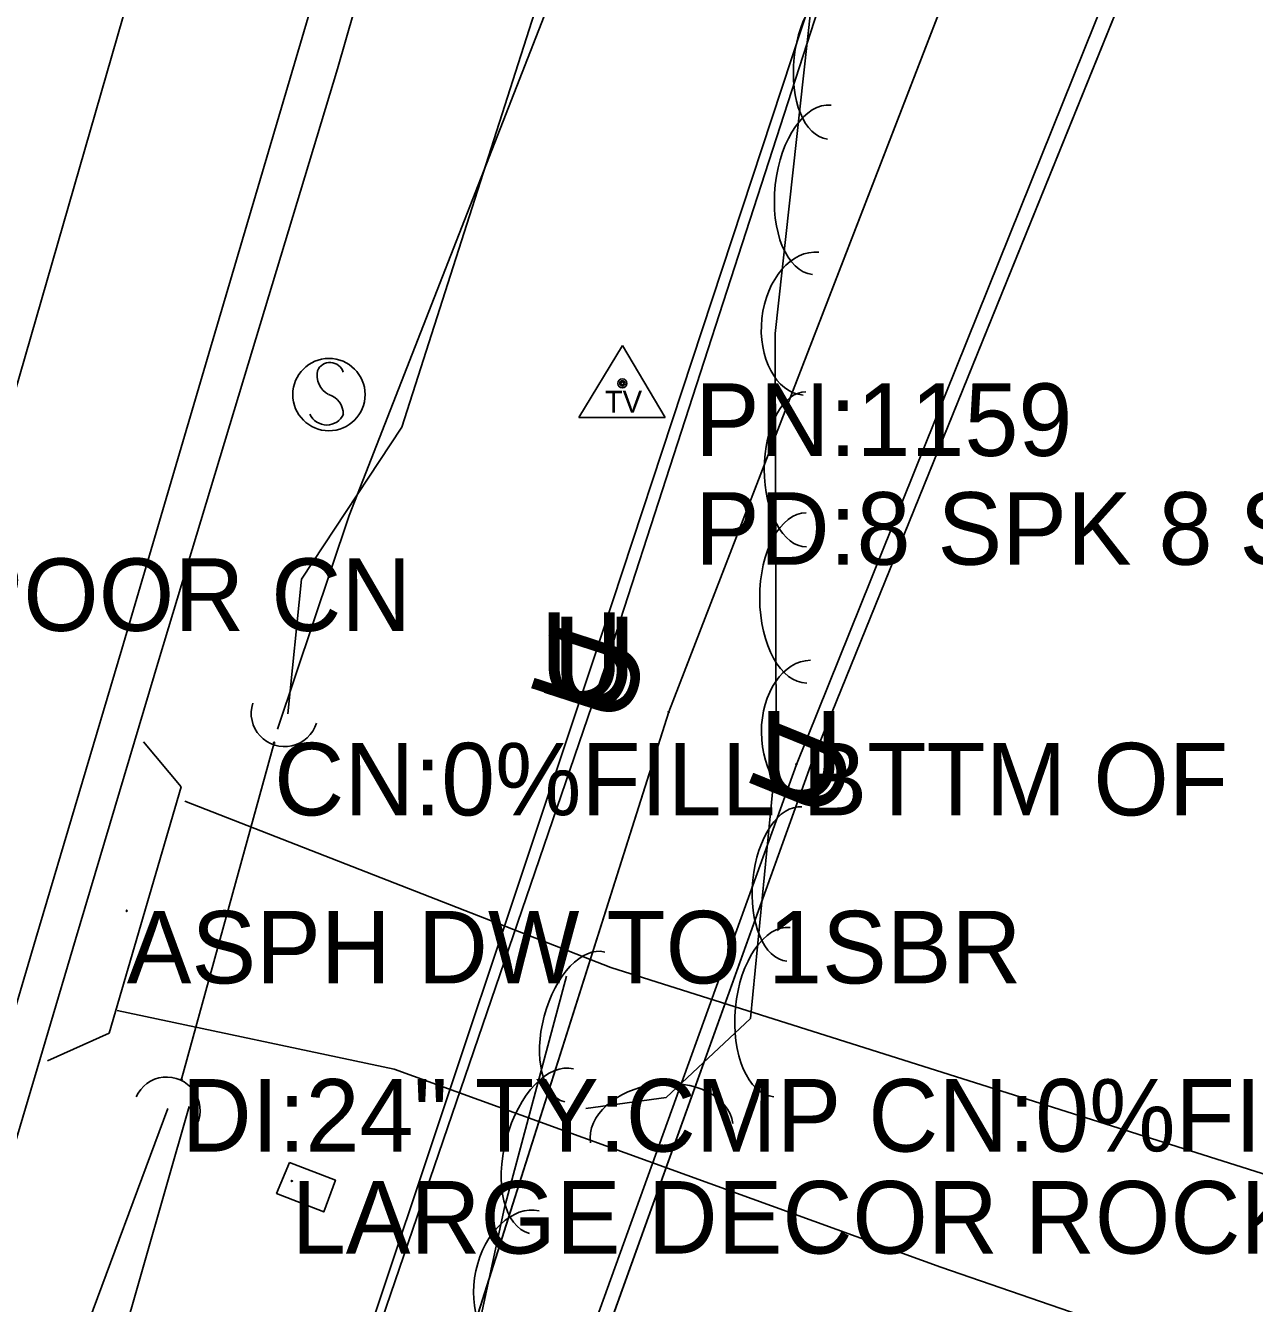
# Model space of a CAD drawing. Extents: x 954793 to 988390, y 1867850 to 1924428.
# Drawn here: x 961111.1 to 961195.8, y 1905934.5 to 1906022.6 of the extents above; entities that cross this region are included whole.
import ezdxf

# ---------------------------------------------------------------- set-up
doc = ezdxf.new("R2010")
doc.units = 0
for name, color, linetype in [('Default', 7, 'Continuous'), ('S_CROSS_DRAIN', 7, 'Continuous'), ('S_DITCHLINE', 7, 'Continuous'), ('S_DRG_PT_SYM', 7, 'Continuous'), ('S_DRIVEWAY', 7, 'Continuous'), ('S_EDGE_CONCRETE', 7, 'Continuous'), ('S_EDGE_PAVEMENT', 7, 'Continuous'), ('S_FIBER_OPTIC_CABLE', 7, 'Continuous'), ('S_MSC_PT_SYM', 7, 'Continuous'), ('S_PAVEMENT_CROWN', 7, 'Continuous'), ('S_SECONDARY_CTL', 7, 'Continuous'), ('S_SECONDARY_CTL_ANNOT', 7, 'Continuous'), ('S_SHOULDER', 7, 'Continuous'), ('S_SIDE_DRAIN', 7, 'Continuous'), ('S_SIDE_DRAIN_ANNOT', 7, 'Continuous'), ('S_SIGN', 7, 'Continuous'), ('S_STREAM', 7, 'Continuous'), ('S_SURVEY_TEXT_ANNOT', 7, 'Continuous'), ('S_TREE', 7, 'Continuous'), ('S_UNDERGROUND_CABLE', 7, 'Continuous'), ('S_UTL_PT_SYM', 7, 'Continuous'), ('S_WATER_UTILITIES', 7, 'Continuous')]:
    doc.layers.add(name, color=color, linetype=linetype)

msp = doc.modelspace()

# ---------------------------------------------------------------- linework, layer by layer
at = {"layer": 'S_CROSS_DRAIN'}
for centre, start, end in [((961128.96, 1905975.23), 162.58525, 342.91443), ((961120.837, 1905947.85), 335.96527, 156.29446)]:
    msp.add_arc(centre, 2.3, start, end, dxfattribs=at)
at = {"layer": 'S_DITCHLINE'}
for points in [[(961129.18, 1905975.188), (961130.136, 1905984.462), (961137.044, 1905994.957), (961141.521, 1906008.944), (961145.998, 1906022.932), (961150.474, 1906036.919), (961154.951, 1906050.907), (961160.816, 1906068.656), (961166.682, 1906086.405), (961172.547, 1906104.154), (961178.413, 1906121.903), (961184.86, 1906136.474), (961191.308, 1906151.044), (961194.924, 1906165.194)], [(961060.215, 1905744.943), (961065.303, 1905762.405), (961070.391, 1905779.868), (961075.479, 1905797.33), (961080.567, 1905814.792), (961085.085, 1905834.323), (961090.929, 1905858.605), (961096.773, 1905882.887), (961102.809, 1905899.163), (961108.845, 1905915.438), (961114.881, 1905931.714), (961120.917, 1905947.989)], [(961061.183, 1905744.784), (961066.495, 1905762.214), (961071.808, 1905779.644), (961077.121, 1905797.073), (961082.433, 1905814.503), (961090.136, 1905832.773), (961096.66, 1905856.896), (961103.185, 1905881.019), (961107.984, 1905897.792), (961112.783, 1905914.564), (961117.581, 1905931.337), (961122.38, 1905948.109)]]:
    msp.add_lwpolyline(points, dxfattribs=at)
at = {"layer": 'S_DRG_PT_SYM'}
for points in [[(961128.243, 1905973.187), (961128.243, 1905973.237), (961128.243, 1905973.187), (961128.193, 1905973.187), (961128.243, 1905973.187), (961128.243, 1905973.137), (961128.243, 1905973.187), (961128.293, 1905973.187)], [(961121.864, 1905950.008), (961121.864, 1905950.058), (961121.864, 1905950.008), (961121.814, 1905950.008), (961121.864, 1905950.008), (961121.864, 1905949.958), (961121.864, 1905950.008), (961121.914, 1905950.008)]]:
    msp.add_lwpolyline(points, dxfattribs=at)
for points in [[(961128.243, 1905973.187), (961128.195, 1905973.2), (961128.243, 1905973.187), (961128.23, 1905973.139), (961128.243, 1905973.187), (961128.291, 1905973.174), (961128.243, 1905973.187), (961128.256, 1905973.235)], [(961128.243, 1905973.187), (961128.195, 1905973.2), (961128.243, 1905973.187), (961128.23, 1905973.139), (961128.243, 1905973.187), (961128.291, 1905973.174), (961128.243, 1905973.187), (961128.256, 1905973.235)], [(961121.864, 1905950.008), (961121.816, 1905950.022), (961121.864, 1905950.008), (961121.851, 1905949.96), (961121.864, 1905950.008), (961121.913, 1905949.995), (961121.864, 1905950.008), (961121.878, 1905950.057)], [(961121.864, 1905950.008), (961121.816, 1905950.022), (961121.864, 1905950.008), (961121.851, 1905949.96), (961121.864, 1905950.008), (961121.913, 1905949.995), (961121.864, 1905950.008), (961121.878, 1905950.057)]]:
    msp.add_lwpolyline(points, close=True, dxfattribs=at)
at = {"layer": 'S_DRIVEWAY'}
for points in [[(961119.246, 1905973.25), (961121.829, 1905970.159)], [(961116.874, 1905953.163), (961121.829, 1905970.159)], [(961296.101, 1905908.22), (961245.91, 1905924.921), (961198.101, 1905942.953), (961151.444, 1905957.691), (961122.087, 1905969.17)], [(961117.428, 1905954.727), (961136.52, 1905950.688), (961174.199, 1905937.044), (961189.272, 1905931.845), (961190.701, 1905910.589), (961190.902, 1905906.512), (961191.873, 1905904.938), (961194.153, 1905903.563), (961214.459, 1905896.764)], [(961112.615, 1905951.267), (961116.874, 1905953.163)]]:
    msp.add_lwpolyline(points, dxfattribs=at)
at = {"layer": 'S_EDGE_CONCRETE'}
msp.add_lwpolyline([(961129.301, 1905944.265), (961128.415, 1905942.127), (961131.658, 1905940.847), (961132.469, 1905943.044)], close=True, dxfattribs=at)
at = {"layer": 'S_EDGE_PAVEMENT'}
msp.add_lwpolyline([(961059.501, 1905778.095), (961063.196, 1905791.462), (961068.574, 1905810.915), (961074.557, 1905832.011), (961080.539, 1905853.106), (961086.72, 1905874.132), (961092.901, 1905895.158), (961099.405, 1905917.452), (961105.908, 1905939.746), (961111.82, 1905959.697), (961117.732, 1905979.649), (961123.745, 1906000.037), (961129.759, 1906020.426), (961135.778, 1906040.836), (961141.798, 1906061.247), (961146.962, 1906078.606), (961152.126, 1906095.965), (961158.226, 1906116.731), (961164.327, 1906137.496), (961170.227, 1906157.296), (961176.128, 1906177.097), (961181.983, 1906196.97), (961187.837, 1906216.843)], dxfattribs=at)
at = {"layer": 'S_FIBER_OPTIC_CABLE'}
for p, q in [((961164.243, 1905971.704), (961188.563, 1906032.157)), ((961132.892, 1905884.854), (961164.243, 1905971.704))]:
    msp.add_line(p, q, dxfattribs=at)
msp.add_lwpolyline([(961026.414, 1904948.637), (961017.369, 1904982.587), (961011.819, 1905055.257), (961016.601, 1905138.531), (961017.468, 1905193.437), (961017.277, 1905224.85), (961027.258, 1905262.094), (961046.136, 1905280.89), (961043.588, 1905375.147), (961039.349, 1905456.04), (961041.723, 1905513.175), (961045.689, 1905529.363), (961064.975, 1905556.232), (961068.353, 1905571.617), (961066.892, 1905584.495), (961064.167, 1905622.208), (961068.799, 1905682.724), (961097.338, 1905766.72), (961110.99, 1905817.563), (961132.892, 1905884.854), (961164.243, 1905971.704), (961188.563, 1906032.157), (961262.109, 1906149.746)], dxfattribs=at)
msp.add_lwpolyline([(961026.414, 1904948.637), (961017.369, 1904982.587), (961011.819, 1905055.257), (961016.601, 1905138.531), (961017.468, 1905193.437), (961017.277, 1905224.85), (961027.258, 1905262.094), (961046.136, 1905280.89), (961043.588, 1905375.147), (961039.349, 1905456.04), (961041.723, 1905513.175), (961045.689, 1905529.363), (961064.975, 1905556.232), (961068.353, 1905571.617), (961066.892, 1905584.495), (961064.167, 1905622.208), (961068.799, 1905682.724), (961097.338, 1905766.72), (961110.99, 1905817.563), (961132.892, 1905884.854), (961164.243, 1905971.704), (961188.563, 1906032.157), (961262.109, 1906149.746)], dxfattribs=at)
at = {"layer": 'S_MSC_PT_SYM'}
for points in [[(961118.082, 1905961.603), (961118.082, 1905961.653), (961118.082, 1905961.603), (961118.032, 1905961.603), (961118.082, 1905961.603), (961118.082, 1905961.553), (961118.082, 1905961.603), (961118.132, 1905961.603)], [(961118.082, 1905961.603), (961118.082, 1905961.653), (961118.082, 1905961.603), (961118.032, 1905961.603), (961118.082, 1905961.603), (961118.082, 1905961.553), (961118.082, 1905961.603), (961118.132, 1905961.603)], [(961129.459, 1905942.977), (961129.459, 1905943.027), (961129.459, 1905942.977), (961129.409, 1905942.977), (961129.459, 1905942.977), (961129.459, 1905942.927), (961129.459, 1905942.977), (961129.509, 1905942.977)], [(961129.459, 1905942.977), (961129.459, 1905943.027), (961129.459, 1905942.977), (961129.409, 1905942.977), (961129.459, 1905942.977), (961129.459, 1905942.927), (961129.459, 1905942.977), (961129.509, 1905942.977)]]:
    msp.add_lwpolyline(points, close=True, dxfattribs=at)
for points in [[(961118.082, 1905961.603), (961118.082, 1905961.653), (961118.082, 1905961.603), (961118.032, 1905961.603), (961118.082, 1905961.603), (961118.082, 1905961.553), (961118.082, 1905961.603), (961118.132, 1905961.603)], [(961129.459, 1905942.977), (961129.459, 1905943.027), (961129.459, 1905942.977), (961129.409, 1905942.977), (961129.459, 1905942.977), (961129.459, 1905942.927), (961129.459, 1905942.977), (961129.509, 1905942.977)]]:
    msp.add_lwpolyline(points, dxfattribs=at)
at = {"layer": 'S_PAVEMENT_CROWN'}
msp.add_lwpolyline([(961045.692, 1905774.257), (961051.222, 1905794.405), (961056.753, 1905814.553), (961062.701, 1905835.209), (961068.648, 1905855.865), (961074.923, 1905877.26), (961081.198, 1905898.655), (961087.38, 1905919.534), (961093.562, 1905940.414), (961099.888, 1905961.707), (961106.214, 1905983), (961112.203, 1906003.736), (961118.191, 1906024.473), (961123.855, 1906043.594), (961129.52, 1906062.715), (961135.06, 1906081.232), (961140.6, 1906099.749), (961146.853, 1906120.651), (961153.107, 1906141.553), (961158.918, 1906161.262), (961164.729, 1906180.972), (961170.649, 1906200.778), (961176.57, 1906220.585)], dxfattribs=at)
at = {"layer": 'S_SECONDARY_CTL'}
for p, q in [((961152.244, 1906000.578), (961149.234, 1905995.624)), ((961152.244, 1906000.578), (961155.191, 1905995.624)), ((961149.234, 1905995.624), (961155.191, 1905995.624))]:
    msp.add_line(p, q, dxfattribs=at)
for radius in [0.311, 0.183, 0.103]:
    msp.add_circle((961152.244, 1905997.968), radius, dxfattribs=at)
at = {"layer": 'S_SHOULDER'}
msp.add_lwpolyline([(961061.53, 1905777.008), (961065.543, 1905790.797), (961071.149, 1905810.063), (961077.06, 1905831.047), (961082.972, 1905852.032), (961089.167, 1905873.293), (961095.361, 1905894.554), (961102.078, 1905917.445), (961108.795, 1905940.336), (961114.544, 1905959.623), (961120.293, 1905978.91), (961126.454, 1905999.284), (961132.614, 1906019.658), (961138.502, 1906040.151), (961144.389, 1906060.644), (961149.609, 1906077.911), (961154.83, 1906095.178), (961161.033, 1906115.566), (961167.236, 1906135.953), (961169.91, 1906145.635), (961174.041, 1906161.079), (961178.172, 1906176.523), (961184.445, 1906196.28), (961190.718, 1906216.037)], dxfattribs=at)
at = {"layer": 'S_SIDE_DRAIN'}
msp.add_line((961121.864, 1905950.008), (961128.243, 1905973.187), dxfattribs=at)
msp.add_lwpolyline([(961121.864, 1905950.008), (961128.243, 1905973.187)], dxfattribs=at)
msp.add_lwpolyline([(961121.864, 1905950.008), (961128.243, 1905973.187)], dxfattribs=at)
at = {"layer": 'S_SIGN'}
msp.add_circle((961132.02, 1905997.198), 2.494, dxfattribs=at)
for centre, radius, start, end in [((961132.094, 1905998.466), 0.95, 16.52582, 156.89569), ((961132.706, 1905998.525), 1.503, 167.11961, 241.98129), ((961131.608, 1905995.856), 1.398, 358.65289, 73.70634), ((961131.867, 1905996.376), 1.275, 204.64102, 335.35898)]:
    msp.add_arc(centre, radius, start, end, dxfattribs=at)
at = {"layer": 'S_STREAM'}
msp.add_lwpolyline([(961128.481, 1905974.139), (961133.42, 1905988.873), (961146.853, 1906023.29), (961155.667, 1906050.873), (961167.729, 1906085.935), (961181.678, 1906131.246), (961190.307, 1906152.691), (961193.786, 1906159.569), (961195.042, 1906166.534)], dxfattribs=at)
at = {"layer": 'S_TREE'}
for points in [[(961149.717, 1905947.977), (961155.258, 1905948.73), (961161.079, 1905954.184), (961162.847, 1905972.394), (961162.769, 1906001.409), (961165.231, 1906023.769), (961167.597, 1906030.415), (961177.41, 1906046.959), (961187.224, 1906054.312), (961192.893, 1906070.61), (961195.056, 1906096.656), (961195.57, 1906124.78), (961197.722, 1906144.345), (961210.193, 1906184.689), (961219.088, 1906219.194)], [(961095.873, 1905771.677), (961101.648, 1905792.34), (961111.197, 1905822.337), (961117.452, 1905845.686), (961123.47, 1905862.287), (961140.579, 1905924.778), (961144.127, 1905941.149), (961148.391, 1905957.107)]]:
    msp.add_lwpolyline(points, dxfattribs=at)
for centre, major_axis, ratio in [((961166.963, 1906020.126), (-0.585, -5.314), 0.540699), ((961165.993, 1906011.311), (-0.642, -5.833), 0.55008), ((961165.24, 1906002.08), (-0.542, -4.926), 0.685311), ((961164.915, 1905992.048), (0.014, -5.346), 0.540699), ((961164.939, 1905983.18), (0.016, -5.868), 0.55008), ((961165.225, 1905973.922), (0.013, -4.955), 0.685311), ((961164.109, 1905963.448), (-0.517, -5.321), 0.540699), ((961163.252, 1905954.622), (-0.567, -5.841), 0.55008), ((961149.65, 1905953.6), (-1.38, -5.165), 0.540699), ((961147.36, 1905945.033), (-1.515, -5.67), 0.55008), ((961154.949, 1905946.284), (-4.91, -0.667), 0.685311), ((961145.466, 1905936.078), (-1.05, -4.843), 0.685311)]:
    msp.add_ellipse(centre, major_axis=major_axis, ratio=ratio, start_param=3.141593, end_param=6.283185, dxfattribs=at)
at = {"layer": 'S_UNDERGROUND_CABLE'}
for p, q in [((961150.178, 1905978.736), (961170.903, 1906041.604)), ((961151.052, 1905978.437), (961171.492, 1906041.573)), ((961165.317, 1905971.926), (961189.544, 1906031.665)), ((961122.683, 1905896.294), (961150.178, 1905978.736)), ((961122.935, 1905896.129), (961151.052, 1905978.437)), ((961133.816, 1905884.197), (961165.317, 1905971.926))]:
    msp.add_line(p, q, dxfattribs=at)
for points in [[(961017.856, 1904908.457), (961015.885, 1904941.507), (961005.937, 1904974.057), (960999.55, 1905055.876), (961001.902, 1905134.038), (961007.432, 1905195.766), (961009.84, 1905254.085), (961011.897, 1905344.409), (961013.819, 1905431.572), (961016.121, 1905461.565), (961020.884, 1905544.239), (961037.019, 1905625.358), (961046.38, 1905663.741), (961054.039, 1905678.824), (961068.032, 1905730.244), (961081.989, 1905759.219), (961099.968, 1905821.206), (961122.683, 1905896.294), (961150.178, 1905978.736), (961170.903, 1906041.604), (961202.059, 1906097.637), (961216.094, 1906117.433), (961239.648, 1906156.812)], [(961017.856, 1904908.457), (961015.885, 1904941.507), (961005.937, 1904974.057), (960999.55, 1905055.876), (961001.902, 1905134.038), (961007.432, 1905195.766), (961009.84, 1905254.085), (961011.897, 1905344.409), (961013.819, 1905431.572), (961016.121, 1905461.565), (961020.884, 1905544.239), (961037.019, 1905625.358), (961046.38, 1905663.741), (961054.039, 1905678.824), (961068.032, 1905730.244), (961081.989, 1905759.219), (961099.968, 1905821.206), (961122.683, 1905896.294), (961150.178, 1905978.736), (961170.903, 1906041.604), (961202.059, 1906097.637), (961216.094, 1906117.433), (961239.648, 1906156.812)], [(961018.521, 1904908.237), (961016.25, 1904941.651), (961006.406, 1904974.081), (961000.088, 1905055.791), (961002.591, 1905134.184), (961008.144, 1905195.509), (961010.364, 1905253.954), (961012.527, 1905344.234), (961014.305, 1905431.545), (961016.781, 1905461.41), (961021.243, 1905543.936), (961037.472, 1905625.323), (961046.9, 1905663.524), (961054.501, 1905678.7), (961068.525, 1905729.918), (961082.6, 1905758.887), (961100.338, 1905821.137), (961122.935, 1905896.129), (961151.052, 1905978.437), (961171.492, 1906041.573), (961202.633, 1906097.751), (961216.733, 1906116.832), (961239.626, 1906156.767)], [(961018.521, 1904908.237), (961016.25, 1904941.651), (961006.406, 1904974.081), (961000.088, 1905055.791), (961002.591, 1905134.184), (961008.144, 1905195.509), (961010.364, 1905253.954), (961012.527, 1905344.234), (961014.305, 1905431.545), (961016.781, 1905461.41), (961021.243, 1905543.936), (961037.472, 1905625.323), (961046.9, 1905663.524), (961054.501, 1905678.7), (961068.525, 1905729.918), (961082.6, 1905758.887), (961100.338, 1905821.137), (961122.935, 1905896.129), (961151.052, 1905978.437), (961171.492, 1906041.573), (961202.633, 1906097.751), (961216.733, 1906116.832), (961239.626, 1906156.767)], [(961062.236, 1905659.183), (961065.738, 1905659.369), (961069.924, 1905682.488), (961098.401, 1905766.49), (961112.008, 1905817.424), (961133.816, 1905884.197), (961165.317, 1905971.926), (961189.544, 1906031.665), (961255.496, 1906122.597), (961261.765, 1906150.054)], [(961062.236, 1905659.183), (961065.738, 1905659.369), (961069.924, 1905682.488), (961098.401, 1905766.49), (961112.008, 1905817.424), (961133.816, 1905884.197), (961165.317, 1905971.926), (961189.544, 1906031.665), (961255.496, 1906122.597), (961261.765, 1906150.054)]]:
    msp.add_lwpolyline(points, dxfattribs=at)
at = {"layer": 'S_UTL_PT_SYM'}
for points in [[(961155.443, 1905975.316), (961155.443, 1905975.366), (961155.443, 1905975.316), (961155.393, 1905975.316), (961155.443, 1905975.316), (961155.443, 1905975.266), (961155.443, 1905975.316), (961155.493, 1905975.316)], [(961164.243, 1905971.704), (961164.243, 1905971.754), (961164.243, 1905971.704), (961164.193, 1905971.704), (961164.243, 1905971.704), (961164.243, 1905971.654), (961164.243, 1905971.704), (961164.293, 1905971.704)]]:
    msp.add_lwpolyline(points, dxfattribs=at)
for points in [[(961155.443, 1905975.316), (961155.396, 1905975.334), (961155.443, 1905975.316), (961155.425, 1905975.27), (961155.443, 1905975.316), (961155.489, 1905975.298), (961155.443, 1905975.316), (961155.461, 1905975.363)], [(961155.443, 1905975.316), (961155.396, 1905975.334), (961155.443, 1905975.316), (961155.425, 1905975.27), (961155.443, 1905975.316), (961155.489, 1905975.298), (961155.443, 1905975.316), (961155.461, 1905975.363)], [(961164.243, 1905971.704), (961164.196, 1905971.723), (961164.243, 1905971.704), (961164.224, 1905971.658), (961164.243, 1905971.704), (961164.289, 1905971.685), (961164.243, 1905971.704), (961164.261, 1905971.75)], [(961164.243, 1905971.704), (961164.196, 1905971.723), (961164.243, 1905971.704), (961164.224, 1905971.658), (961164.243, 1905971.704), (961164.289, 1905971.685), (961164.243, 1905971.704), (961164.261, 1905971.75)]]:
    msp.add_lwpolyline(points, close=True, dxfattribs=at)
at = {"layer": 'S_WATER_UTILITIES'}
for p, q in [((961155.443, 1905975.316), (961181.035, 1906041.587)), ((961126.173, 1905882.976), (961155.443, 1905975.316))]:
    msp.add_line(p, q, dxfattribs=at)
msp.add_lwpolyline([(961085.613, 1905467.735), (961056.003, 1905539.166), (961050.341, 1905555.078), (961049.233, 1905594.708), (961068.721, 1905688.655), (961090.923, 1905765.319), (961105.262, 1905813.045), (961126.173, 1905882.976), (961155.443, 1905975.316), (961181.035, 1906041.587), (961226.378, 1906097.408), (961243.025, 1906126.273), (961256.327, 1906154.927)], dxfattribs=at)
msp.add_lwpolyline([(961085.613, 1905467.735), (961056.003, 1905539.166), (961050.341, 1905555.078), (961049.233, 1905594.708), (961068.721, 1905688.655), (961090.923, 1905765.319), (961105.262, 1905813.045), (961126.173, 1905882.976), (961155.443, 1905975.316), (961181.035, 1906041.587), (961226.378, 1906097.408), (961243.025, 1906126.273), (961256.327, 1906154.927)], dxfattribs=at)

# ---------------------------------------------------------------- texts
at = {"layer": 'Default'}
for rotation, p in [(360, (961146.549, 1905976.19)), (360, (961147.422, 1905975.891)), (71.75525, (961151.459, 1905974.492)), (72.06067, (961152.355, 1905974.2)), (360, (961161.687, 1905969.381)), (67.92428, (961166.311, 1905967.606))]:
    msp.add_text('U', height=6, rotation=rotation, dxfattribs=at).set_placement(p)
at = {"layer": 'S_SECONDARY_CTL'}
msp.add_text('TV', height=1.5, rotation=360, dxfattribs=at).set_placement((961151.039, 1905995.957))
at = {"layer": 'S_SECONDARY_CTL_ANNOT'}
for s, p in [('PN:1159', (961157.244, 1905992.968)), ('PD:8 SPK 8 SPIKE', (961157.244, 1905985.468))]:
    msp.add_text(s, height=5, dxfattribs=at).set_placement(p)
at = {"layer": 'S_SIDE_DRAIN_ANNOT'}
for s, p in [('CN:0%FILL BTTM OF PIPE', (961128.243, 1905968.187)), ('DI:24" TY:CMP CN:0%FILL BTTM OF', (961121.864, 1905945.008))]:
    msp.add_text(s, height=5, dxfattribs=at).set_placement(p)
at = {"layer": 'S_SURVEY_TEXT_ANNOT'}
for s, p in [('FENCE NOW POOR CN', (961063.777, 1905980.904)), ('ASPH DW TO 1SBR', (961118.082, 1905956.603)), ('LARGE DECOR ROCK W/ ADD', (961129.459, 1905937.977))]:
    msp.add_text(s, height=5, dxfattribs=at).set_placement(p)

doc.saveas('drawing.dxf')
